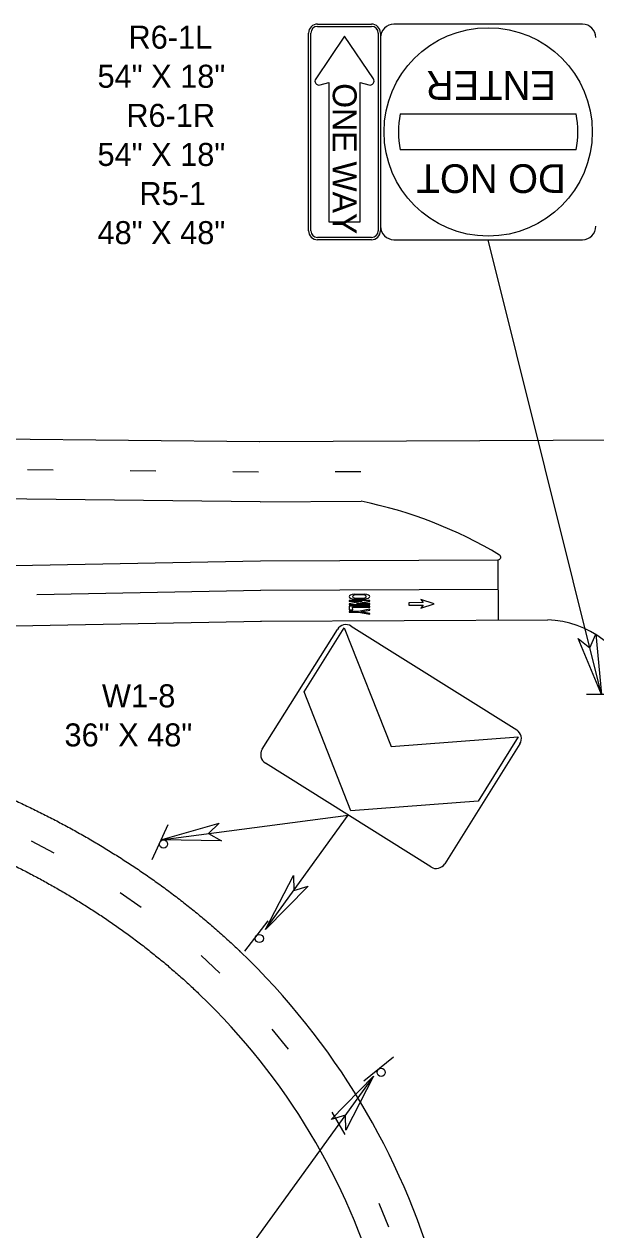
# Model space of a CAD drawing. Extents: x 582908 to 586039, y 1530940 to 1532988.
# Drawn here: x 585300 to 585649, y 1532013 to 1532747 of the extents above; entities that cross this region are included whole.
import ezdxf

# ---------------------------------------------------------------- set-up
doc = ezdxf.new("R2010")
doc.units = 0
for name, color, linetype in [('DirArrowsPavt', 7, 'Continuous'), ('LeaderLine_dp', 7, 'Continuous'), ('PavtMessage', 7, 'Continuous'), ('PMStripe24W', 7, 'Continuous'), ('PMStripe6W', 7, 'Continuous'), ('PMStripe6W(10-30)', 7, 'Continuous'), ('PMStripe6Y', 7, 'Continuous'), ('PMStripe8W', 7, 'Continuous'), ('SignPanel', 7, 'Continuous'), ('SignSupport', 7, 'Continuous'), ('TextLabel', 7, 'Continuous'), ('TextShtNo', 7, 'Continuous')]:
    doc.layers.add(name, color=color, linetype=linetype)

# ---------------------------------------------------------------- blocks, each defined once
blk = doc.blocks.new('ArrTermPnt')
at = {"layer": 'LeaderLine_dp'}
for p, q in [((-0.1, 0), (-0.12, 0.02)), ((-0.12, 0.02), (0, 0)), ((0, 0), (-0.12, -0.02)), ((-0.12, -0.02), (-0.1, 0))]:
    blk.add_line(p, q, dxfattribs=at)

msp = doc.modelspace()

# ---------------------------------------------------------------- linework, layer by layer
at = {"layer": 'DirArrowsPavt'}
for p, q in [((585543.47, 1532394.6), (585534.75, 1532394.56)), ((585534.75, 1532394.56), (585534.75, 1532393)), ((585534.75, 1532393), (585543.48, 1532393.04)), ((585550.11, 1532393.85), (585541.9, 1532396.42)), ((585541.9, 1532396.42), (585543.47, 1532394.6)), ((585541.92, 1532391.21), (585550.11, 1532393.85)), ((585543.48, 1532393.04), (585541.92, 1532391.21))]:
    msp.add_line(p, q, dxfattribs=at)
at = {"layer": 'LeaderLine_dp'}
for p, q in [((585652.03, 1532338.6), (585583, 1532615.55)), ((585644.95, 1532366.99), (585648.51, 1532375.42)), ((585648.51, 1532375.42), (585652.03, 1532338.6)), ((585652.03, 1532338.6), (585637.86, 1532372.76)), ((585637.86, 1532372.76), (585644.95, 1532366.99)), ((585383.65, 1532250.2), (585497.7, 1532265.29)), ((585447.38, 1532195.64), (585497.7, 1532265.29)), ((585383.65, 1532250.2), (585419.19, 1532260.44)), ((585419.19, 1532260.44), (585412.66, 1532254.04)), ((585420.63, 1532249.56), (585383.65, 1532250.2)), ((585412.66, 1532254.04), (585420.63, 1532249.56)), ((585447.38, 1532195.64), (585464.35, 1532228.5)), ((585464.35, 1532228.5), (585464.52, 1532219.36)), ((585473.25, 1532222.08), (585447.38, 1532195.64)), ((585464.52, 1532219.36), (585473.25, 1532222.08)), ((585513.24, 1532106.33), (585360.53, 1531895.82)), ((585487.32, 1532079.94), (585513.24, 1532106.33)), ((585513.24, 1532106.33), (585496.2, 1532073.5)), ((585496.06, 1532082.64), (585487.32, 1532079.94)), ((585496.2, 1532073.5), (585496.06, 1532082.64))]:
    msp.add_line(p, q, dxfattribs=at)
at = {"layer": 'PavtMessage'}
for p, q in [((585501.37, 1532399.82), (585507.8, 1532399.85)), ((585507.82, 1532396.72), (585501.38, 1532396.7)), ((585507.09, 1532399.32), (585502.09, 1532399.3)), ((585502.1, 1532397.22), (585507.1, 1532397.24)), ((585510.85, 1532395.96), (585498.35, 1532395.9)), ((585498.35, 1532395.9), (585498.35, 1532395.38)), ((585498.35, 1532395.38), (585506.17, 1532395.41)), ((585506.17, 1532395.41), (585498.36, 1532393.95)), ((585498.36, 1532393.95), (585498.36, 1532393.43)), ((585498.36, 1532393.43), (585510.86, 1532393.48)), ((585510.87, 1532392.44), (585498.37, 1532392.39)), ((585498.37, 1532392.39), (585498.38, 1532390.3)), ((585498.38, 1532390.3), (585500.46, 1532390.31)), ((585500.45, 1532391.87), (585510.87, 1532391.92)), ((585500.46, 1532390.31), (585500.45, 1532391.87)), ((585502.89, 1532393.97), (585510.85, 1532395.44)), ((585510.86, 1532394), (585502.89, 1532393.97)), ((585510.88, 1532390.62), (585504.11, 1532389.29)), ((585505.52, 1532389.03), (585510.88, 1532390.09)), ((585510.85, 1532395.44), (585510.85, 1532395.96)), ((585510.86, 1532393.48), (585510.86, 1532394)), ((585510.87, 1532391.92), (585510.87, 1532392.44)), ((585510.88, 1532390.09), (585510.88, 1532390.62)), ((585504.11, 1532389.29), (585498.38, 1532389.26)), ((585498.38, 1532389.26), (585498.38, 1532388.74)), ((585498.38, 1532388.74), (585504.11, 1532388.76)), ((585504.11, 1532388.76), (585510.89, 1532387.49)), ((585510.89, 1532388.02), (585505.52, 1532389.03)), ((585510.89, 1532387.49), (585510.89, 1532388.02))]:
    msp.add_line(p, q, dxfattribs=at)
for major_axis, ratio, start_param, end_param in [((6.25, 0.03), 0.291667, 2.111896, 4.171289), ((4.17, 0.02), 0.3125, 2.214297, 4.068888), ((4.17, 0.02), 0.3125, 5.35589, 7.210481), ((6.25, 0.03), 0.291667, 5.253489, 7.312882)]:
    msp.add_ellipse((585504.59, 1532398.27), major_axis=major_axis, ratio=ratio, start_param=start_param, end_param=end_param, dxfattribs=at)
at = {"layer": 'PMStripe24W'}
msp.add_line((585589.29, 1532384), (585589.13, 1532420.71), dxfattribs=at)
at = {"layer": 'PMStripe6W'}
for p, q in [((585307.97, 1532399.45), (585444.61, 1532402.11)), ((585444.33, 1532402.1), (585589.21, 1532402.75))]:
    msp.add_line(p, q, dxfattribs=at)
msp.add_arc((585125.59, 1531862.24), 407.03, 225.07112, 46.1803, dxfattribs=at)
msp.add_spline([(585187.73, 1532274.87), (585194.55, 1532272.95), (585202.66, 1532270.56), (585210.74, 1532268.06), (585218.79, 1532265.46), (585226.8, 1532262.76), (585234.78, 1532259.94), (585242.71, 1532257.01), (585250.6, 1532253.96), (585258.44, 1532250.81), (585266.24, 1532247.53), (585273.99, 1532244.14), (585281.68, 1532240.62), (585289.32, 1532236.99), (585296.9, 1532233.24), (585304.42, 1532229.36), (585311.87, 1532225.35), (585319.25, 1532221.23), (585326.57, 1532216.97), (585333.8, 1532212.59), (585340.96, 1532208.08), (585348.04, 1532203.45), (585355.03, 1532198.68), (585361.93, 1532193.79), (585368.74, 1532188.77), (585375.45, 1532183.62), (585382.06, 1532178.33), (585388.57, 1532172.92), (585394.96, 1532167.38), (585401.25, 1532161.72), (585407.4, 1532155.93)], degree=3, dxfattribs=at)
at = {"layer": 'PMStripe6W(10-30)'}
for p, q in [((585318.01, 1532475.31), (585302.39, 1532475.47)), ((585380.51, 1532474.64), (585364.89, 1532474.81)), ((585443.01, 1532473.98), (585427.38, 1532474.15)), ((585505.51, 1532474.25), (585489.88, 1532474.18)), ((585318.63, 1532242.13), (585304.79, 1532249.38)), ((585371.57, 1532208.99), (585358.74, 1532217.91)), ((585419.62, 1532169.1), (585408.15, 1532179.71)), ((585461.31, 1532122.85), (585451.5, 1532135.01)), ((585495.87, 1532070.84), (585487.95, 1532084.31)), ((585522.44, 1532014.33), (585516.58, 1532028.82))]:
    msp.add_line(p, q, dxfattribs=at)
at = {"layer": 'PMStripe6Y'}
for p, q in [((585444.1, 1532456.01), (584975.33, 1532460.96)), ((585444.09, 1532456.01), (585505.59, 1532456.28)), ((584975.55, 1532410.96), (585444.26, 1532420.07)), ((585444.26, 1532420.07), (585589.13, 1532420.71))]:
    msp.add_line(p, q, dxfattribs=at)
for centre, radius, start, end in [((585452.59, 1532194.23), 267.36, 59.07703, 78.56614), ((585589.12, 1532422.28), 1.56, 270.25398, 56.87518), ((585125.59, 1531862.24), 442.97, 225.02103, 46.23038)]:
    msp.add_arc(centre, radius, start, end, dxfattribs=at)
msp.add_spline([(585196.71, 1532309.67), (585204.49, 1532307.48), (585213.04, 1532304.97), (585221.57, 1532302.33), (585230.07, 1532299.59), (585238.55, 1532296.72), (585246.99, 1532293.74), (585255.4, 1532290.63), (585263.78, 1532287.4), (585272.11, 1532284.04), (585280.41, 1532280.56), (585288.66, 1532276.94), (585296.87, 1532273.2), (585305.02, 1532269.32), (585313.12, 1532265.31), (585321.16, 1532261.16), (585329.14, 1532256.87), (585337.06, 1532252.45), (585344.91, 1532247.88), (585352.68, 1532243.17), (585360.38, 1532238.32), (585368.01, 1532233.33), (585375.54, 1532228.19), (585382.99, 1532222.91), (585390.35, 1532217.48), (585397.61, 1532211.91), (585404.77, 1532206.19), (585411.82, 1532200.32), (585418.76, 1532194.31), (585425.59, 1532188.15), (585432.02, 1532182.11)], degree=3, dxfattribs=at)
at = {"layer": 'PMStripe8W'}
for p, q in [((584974.87, 1532497.68), (585443.65, 1532492.73)), ((584975.98, 1532374.25), (585444.98, 1532383.36)), ((585444.41, 1532383.35), (585619.27, 1532384.13))]:
    msp.add_line(p, q, dxfattribs=at)
msp.add_lwpolyline([(585443.93, 1532492.73), (585890.69, 1532494.71)], dxfattribs=at)
at = {"layer": 'SignPanel'}
for p, q in [((585479.1, 1532746.8), (585511.91, 1532746.8)), ((585479.1, 1532745.43), (585511.91, 1532745.43)), ((585640.43, 1532746.8), (585525.58, 1532746.8)), ((585473.63, 1532621.01), (585473.63, 1532741.33)), ((585475, 1532621.01), (585475, 1532741.33)), ((585495.5, 1532739.5), (585477.93, 1532713.57)), ((585513.07, 1532713.57), (585495.5, 1532739.5)), ((585516.01, 1532741.33), (585516.01, 1532621.01)), ((585517.38, 1532741.33), (585517.38, 1532621.01)), ((585517.38, 1532738.59), (585517.38, 1532623.75)), ((585480.7, 1532709.75), (585485.93, 1532711.25)), ((585485.93, 1532711.25), (585485.93, 1532626.48)), ((585505.07, 1532711.25), (585510.31, 1532709.75)), ((585505.07, 1532626.48), (585505.07, 1532711.25)), ((585529.42, 1532692.11), (585636.59, 1532692.11)), ((585636.59, 1532670.23), (585529.42, 1532670.23)), ((585485.93, 1532626.48), (585505.07, 1532626.48)), ((585511.91, 1532616.91), (585479.1, 1532616.91)), ((585511.91, 1532615.55), (585479.1, 1532615.55)), ((585525.58, 1532615.55), (585640.43, 1532615.55)), ((585470.85, 1532340.22), (585495.36, 1532379.32)), ((585495.36, 1532379.32), (585523.85, 1532306.99)), ((585499.34, 1532267.9), (585470.85, 1532340.22)), ((585523.85, 1532306.99), (585601.35, 1532312.86)), ((585601.35, 1532312.86), (585576.84, 1532273.77)), ((585576.84, 1532273.77), (585499.34, 1532267.9))]:
    msp.add_line(p, q, dxfattribs=at)
for points in [[(585445.37, 1532305.37), (585491.12, 1532378.34)], [(585499.6, 1532380.29), (585600.38, 1532317.1)], [(585602.32, 1532308.62), (585556.57, 1532235.65)], [(585548.09, 1532233.7), (585447.31, 1532296.89)]]:
    msp.add_lwpolyline(points, dxfattribs=at)
msp.add_circle((585583, 1532681.17), 63.44, dxfattribs=at)
for centre, radius, start, end in [((585479.1, 1532741.33), 5.47, 90, 180), ((585479.1, 1532741.33), 4.1, 90, 180), ((585511.91, 1532741.33), 5.47, 360, 90), ((585511.91, 1532741.33), 4.1, 360, 90), ((585525.58, 1532738.59), 8.2, 90, 180), ((585640.43, 1532738.59), 8.2, 360, 90), ((585480.01, 1532712.16), 2.51, 145.86682, 285.95459), ((585511, 1532712.16), 2.51, 254.06111, 34.11297), ((585583, 1532681.17), 54.69, 168.46307, 191.53692), ((585583, 1532681.17), 54.69, 348.46307, 11.53692), ((585479.1, 1532621.01), 5.47, 180, 270), ((585479.1, 1532621.01), 4.1, 180, 270), ((585511.91, 1532621.01), 5.47, 270, 360), ((585511.91, 1532621.01), 4.1, 270, 360), ((585525.58, 1532623.75), 8.2, 180, 270), ((585640.43, 1532623.75), 8.2, 270, 360), ((585496.34, 1532375.07), 6.15, 57.91267, 147.91267), ((585597.11, 1532311.89), 6.15, 327.91267, 57.91267), ((585450.58, 1532302.1), 6.15, 147.91267, 237.91267), ((585551.36, 1532238.91), 6.15, 237.91267, 327.91267)]:
    msp.add_arc(centre, radius, start, end, dxfattribs=at)
at = {"layer": 'SignSupport'}
for p, q in [((585666.16, 1532338.6), (585642.89, 1532338.6)), ((585387.77, 1532259.28), (585378.16, 1532238.08)), ((585448.69, 1532200.91), (585434.62, 1532182.37)), ((585525.26, 1532117.89), (585507.17, 1532103.25))]:
    msp.add_line(p, q, dxfattribs=at)
for centre in [(585385.24, 1532247.65), (585443.64, 1532190.13), (585517.79, 1532108.63)]:
    msp.add_circle(centre, 2.49, dxfattribs=at)
at = {"layer": 'TextShtNo'}
for centre, radius, start, end in [((585589.12, 1532422.28), 1.56, 270.25398, 56.87518), ((585617.15, 1532324.88), 59.29, 18.08613, 87.94747)]:
    msp.add_arc(centre, radius, start, end, dxfattribs=at)

# ---------------------------------------------------------------- block references
at = {"layer": 'TextLabel', "yscale": 1.9442318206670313}
for p, xscale, rotation in [((585383.65, 1532250.2), 2.041666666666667, -172.45937017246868), ((585447.38, 1532195.64), 2.041666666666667, -125.84652121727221), ((585513.24, 1532106.33), 2.0416666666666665, 54.041828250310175)]:
    msp.add_blockref('ArrTermPnt', p, dxfattribs=dict(at, xscale=xscale, rotation=rotation))

# ---------------------------------------------------------------- texts
at = {"layer": 'SignPanel'}
for s, height, rotation, p in [('ENTER', 17.482, 180, (585624.29, 1532718.18)), ('ONE WAY', 14.567, 270, (585488.33, 1532710.83)), ('DO NOT', 17.482, 180, (585630.25, 1532661.48))]:
    msp.add_text(s, height=height, rotation=rotation, dxfattribs=at).set_placement(p)
at = {"layer": 'TextLabel'}
for s, p in [('R6-1L', (585363.9, 1532731.85)), ('54" X 18"', (585345.02, 1532708.05)), ('R6-1R', (585362.58, 1532684.25)), ('54" X 18"', (585345.02, 1532660.45)), ('R5-1', (585370.53, 1532636.65)), ('48" X 48"', (585345.02, 1532612.85))]:
    msp.add_text(s, height=14, rotation=360, dxfattribs=at).set_placement(p)
for s, p in [('W1-8', (585347.72, 1532330.87)), ('36" X 48"', (585324.91, 1532307.07))]:
    msp.add_text(s, height=14, dxfattribs=at).set_placement(p)

doc.saveas('drawing.dxf')
